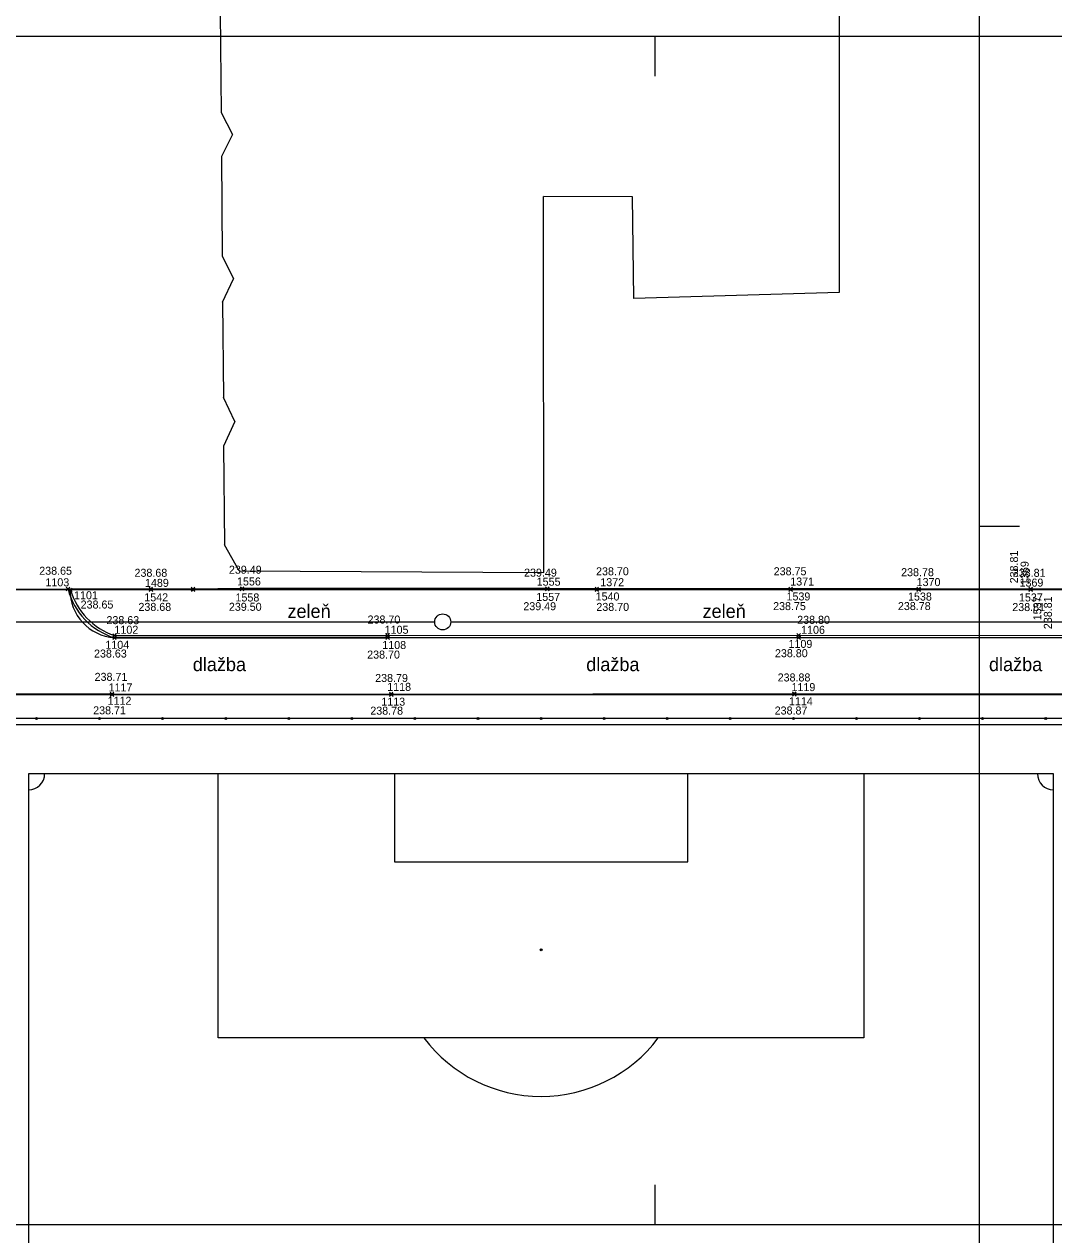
# Model space of a CAD drawing. Extents: x -264205 to -263659, y -1242401 to -1241986.
# Drawn here: x -264039.8 to -263975.5, y -1242219.8 to -1242144.2 of the extents above; entities that cross this region are included whole.
import ezdxf

# ---------------------------------------------------------------- set-up
doc = ezdxf.new("R2010")
doc.units = 0
for name, color, linetype in [('BOD_CISLO_2-1', 7, 'Continuous'), ('BOD_CISLO_2-3', 7, 'Continuous'), ('BOD_SYMBOL_2-1', 7, 'Continuous'), ('BOD_SYMBOL_2-3', 7, 'Continuous'), ('BOD_VYSKA_2-1', 7, 'Continuous'), ('BOD_VYSKA_2-3', 7, 'Continuous'), ('POPIS_2-1', 7, 'Continuous'), ('PROJEKT_OBRUBNIKY_KOMUNIKACIE', 7, 'Continuous'), ('RAM_NA_TLAC_2-1_1-250', 7, 'Continuous'), ('RAM_NA_TLAC_2-3_1-250', 7, 'Continuous'), ('SITUACIA_DSP_2D', 7, 'Continuous'), ('SO_20-4_OBRUBNIKY_HORNA_HRANA', 7, 'Continuous')]:
    doc.layers.add(name, color=color, linetype=linetype)

msp = doc.modelspace()

# ---------------------------------------------------------------- linework, layer by layer
at = {"layer": 'BOD_SYMBOL_2-1'}
for p, q in [((-264037.17, -1242179.556), (-264036.948, -1242179.336)), ((-264036.948, -1242179.556), (-264037.17, -1242179.336)), ((-264037.012, -1242179.6), (-264036.791, -1242179.38)), ((-264036.791, -1242179.6), (-264037.012, -1242179.38)), ((-264032, -1242179.555), (-264031.779, -1242179.333)), ((-264031.779, -1242179.555), (-264032, -1242179.333)), ((-264031.993, -1242179.603), (-264031.772, -1242179.383)), ((-264031.772, -1242179.603), (-264031.993, -1242179.383)), ((-264029.359, -1242179.559), (-264029.138, -1242179.338)), ((-264029.138, -1242179.559), (-264029.359, -1242179.338)), ((-264029.357, -1242179.6), (-264029.136, -1242179.379)), ((-264029.136, -1242179.6), (-264029.357, -1242179.379)), ((-264026.3, -1242179.565), (-264026.079, -1242179.343)), ((-264026.079, -1242179.565), (-264026.3, -1242179.343)), ((-264026.297, -1242179.519), (-264026.076, -1242179.299)), ((-264026.076, -1242179.519), (-264026.297, -1242179.299)), ((-264007.234, -1242179.525), (-264007.013, -1242179.305)), ((-264007.013, -1242179.525), (-264007.234, -1242179.305)), ((-264007.234, -1242179.566), (-264007.013, -1242179.346)), ((-264007.013, -1242179.566), (-264007.234, -1242179.346)), ((-264004.149, -1242179.552), (-264003.927, -1242179.33)), ((-264003.927, -1242179.552), (-264004.149, -1242179.33)), ((-264004.147, -1242179.599), (-264003.926, -1242179.377)), ((-264003.926, -1242179.599), (-264004.147, -1242179.377)), ((-263992.045, -1242179.593), (-263991.823, -1242179.372)), ((-263991.823, -1242179.593), (-263992.045, -1242179.372)), ((-263992.042, -1242179.546), (-263991.821, -1242179.325)), ((-263991.821, -1242179.546), (-263992.042, -1242179.325)), ((-263984.051, -1242179.595), (-263983.829, -1242179.373)), ((-263983.829, -1242179.595), (-263984.051, -1242179.373)), ((-263984.047, -1242179.551), (-263983.826, -1242179.329)), ((-263983.826, -1242179.551), (-263984.047, -1242179.329)), ((-263977.055, -1242179.556), (-263976.834, -1242179.335)), ((-263976.834, -1242179.556), (-263977.055, -1242179.335)), ((-263977.054, -1242179.603), (-263976.833, -1242179.382)), ((-263976.833, -1242179.603), (-263977.054, -1242179.382)), ((-264034.27, -1242182.455), (-264034.049, -1242182.235)), ((-264034.049, -1242182.455), (-264034.27, -1242182.235)), ((-264034.27, -1242182.602), (-264034.049, -1242182.38)), ((-264034.049, -1242182.602), (-264034.27, -1242182.38)), ((-264017.219, -1242182.458), (-264016.997, -1242182.237)), ((-264016.997, -1242182.458), (-264017.219, -1242182.237)), ((-264017.208, -1242182.597), (-264016.986, -1242182.377)), ((-264016.986, -1242182.597), (-264017.208, -1242182.377)), ((-263991.541, -1242182.44), (-263991.319, -1242182.218)), ((-263991.319, -1242182.44), (-263991.541, -1242182.218)), ((-263991.54, -1242182.588), (-263991.318, -1242182.367)), ((-263991.318, -1242182.588), (-263991.54, -1242182.367)), ((-264034.425, -1242186.103), (-264034.204, -1242185.882)), ((-264034.204, -1242186.103), (-264034.425, -1242185.882)), ((-264016.99, -1242186.115), (-264016.769, -1242185.894)), ((-264016.769, -1242186.115), (-264016.99, -1242185.894)), ((-263991.824, -1242186.088), (-263991.603, -1242185.867)), ((-263991.603, -1242186.088), (-263991.824, -1242185.867)), ((-264034.419, -1242186.149), (-264034.198, -1242185.927)), ((-264034.198, -1242186.149), (-264034.419, -1242185.927)), ((-264016.984, -1242186.16), (-264016.763, -1242185.94)), ((-264016.763, -1242186.16), (-264016.984, -1242185.94)), ((-263991.818, -1242186.133), (-263991.597, -1242185.913)), ((-263991.597, -1242186.133), (-263991.818, -1242185.913))]:
    msp.add_line(p, q, dxfattribs=at)
at = {"layer": 'BOD_SYMBOL_2-3'}
for p, q in [((-263976.834, -1242179.556), (-263977.055, -1242179.335)), ((-263976.834, -1242179.335), (-263977.055, -1242179.556)), ((-263976.833, -1242179.603), (-263977.054, -1242179.382)), ((-263976.833, -1242179.382), (-263977.054, -1242179.603))]:
    msp.add_line(p, q, dxfattribs=at)
at = {"layer": 'PROJEKT_OBRUBNIKY_KOMUNIKACIE'}
for p, q in [((-263959.468, -1242179.482), (-264131.568, -1242179.482)), ((-264131.568, -1242179.482), (-263959.468, -1242179.482)), ((-263959.468, -1242179.482), (-264077.23, -1242179.482)), ((-263960.118, -1242182.482), (-264034.158, -1242182.482))]:
    msp.add_line(p, q, dxfattribs=at)
msp.add_lwpolyline([(-264042.568, -1242294.032), (-263972.468, -1242294.032), (-263972.468, -1242187.932), (-264042.568, -1242187.932), (-264042.568, -1242294.032)], dxfattribs=at)
msp.add_arc((-264033.951, -1242179.495), 2.994, 179.74999, 266.03136, dxfattribs=at)
at = {"layer": 'RAM_NA_TLAC_2-1_1-250'}
for p, q in [((-264000.413, -1242144.907), (-264000.413, -1242147.407)), ((-264000.413, -1242216.657), (-264000.413, -1242219.157))]:
    msp.add_line(p, q, dxfattribs=at)
msp.add_lwpolyline([(-264147.913, -1242144.907), (-263857.913, -1242144.907), (-263857.913, -1242219.157), (-264147.913, -1242219.157)], close=True, dxfattribs=at)
at = {"layer": 'RAM_NA_TLAC_2-3_1-250'}
msp.add_line((-263980.139, -1242175.511), (-263977.639, -1242175.511), dxfattribs=at)
msp.add_lwpolyline([(-263980.139, -1242275.511), (-263980.139, -1241985.511), (-263905.889, -1241985.511), (-263905.889, -1242275.511)], close=True, dxfattribs=at)
at = {"layer": 'SITUACIA_DSP_2D'}
for p, q in [((-263988.88, -1242124.89), (-263988.91, -1242160.93)), ((-264027.55, -1242143.43), (-264027.5, -1242149.68)), ((-264027.5, -1242149.68), (-264026.79, -1242151.05)), ((-264026.79, -1242151.05), (-264027.48, -1242152.43)), ((-264027.48, -1242152.43), (-264027.43, -1242158.63)), ((-264007.37, -1242157.14), (-264007.36, -1242154.93)), ((-264001.8, -1242154.96), (-264007.36, -1242154.93)), ((-264001.73, -1242161.29), (-264001.8, -1242154.96)), ((-264007.34, -1242178.42), (-264007.37, -1242157.14)), ((-264027.43, -1242158.63), (-264026.72, -1242160.07)), ((-264027.41, -1242161.52), (-264026.72, -1242160.07)), ((-263988.91, -1242160.93), (-264001.73, -1242161.29)), ((-264027.41, -1242161.52), (-264027.36, -1242167.48)), ((-264026.65, -1242168.99), (-264027.36, -1242167.48)), ((-264026.65, -1242168.99), (-264027.34, -1242170.52)), ((-264027.34, -1242170.52), (-264027.29, -1242176.68)), ((-264026.37, -1242178.31), (-264027.29, -1242176.68)), ((-264026.37, -1242178.31), (-264007.34, -1242178.42)), ((-264131.568, -1242179.482), (-263959.468, -1242179.482)), ((-263959.468, -1242179.482), (-264131.568, -1242179.482)), ((-263959.468, -1242179.482), (-264077.23, -1242179.482)), ((-264041.667, -1242181.5), (-264014.161, -1242181.5)), ((-264013.161, -1242181.5), (-263964.161, -1242181.5)), ((-263960.118, -1242182.482), (-264034.158, -1242182.482)), ((-263972.068, -1242187.532), (-264118.068, -1242187.532)), ((-263972.468, -1242187.932), (-264042.568, -1242187.932)), ((-264039.089, -1242187.532), (-264038.969, -1242187.532)), ((-264039.029, -1242187.592), (-264039.029, -1242187.472)), ((-264035.15, -1242187.532), (-264035.03, -1242187.532)), ((-264035.09, -1242187.592), (-264035.09, -1242187.472)), ((-264031.211, -1242187.532), (-264031.091, -1242187.532)), ((-264031.151, -1242187.592), (-264031.151, -1242187.472)), ((-264027.272, -1242187.532), (-264027.152, -1242187.532)), ((-264027.212, -1242187.592), (-264027.212, -1242187.472)), ((-264023.333, -1242187.532), (-264023.213, -1242187.532)), ((-264023.273, -1242187.592), (-264023.273, -1242187.472)), ((-264019.394, -1242187.532), (-264019.274, -1242187.532)), ((-264019.334, -1242187.592), (-264019.334, -1242187.472)), ((-264015.456, -1242187.532), (-264015.336, -1242187.532)), ((-264015.396, -1242187.592), (-264015.396, -1242187.472)), ((-264011.517, -1242187.532), (-264011.397, -1242187.532)), ((-264011.457, -1242187.592), (-264011.457, -1242187.472)), ((-264007.578, -1242187.532), (-264007.458, -1242187.532)), ((-264007.518, -1242187.592), (-264007.518, -1242187.472)), ((-264003.639, -1242187.532), (-264003.519, -1242187.532)), ((-264003.579, -1242187.592), (-264003.579, -1242187.472)), ((-263999.7, -1242187.532), (-263999.58, -1242187.532)), ((-263999.64, -1242187.592), (-263999.64, -1242187.472)), ((-263995.761, -1242187.532), (-263995.641, -1242187.532)), ((-263995.701, -1242187.592), (-263995.701, -1242187.472)), ((-263991.822, -1242187.532), (-263991.702, -1242187.532)), ((-263991.762, -1242187.592), (-263991.762, -1242187.472)), ((-263987.883, -1242187.532), (-263987.763, -1242187.532)), ((-263987.823, -1242187.592), (-263987.823, -1242187.472)), ((-263983.944, -1242187.532), (-263983.824, -1242187.532)), ((-263983.884, -1242187.592), (-263983.884, -1242187.472)), ((-263980.006, -1242187.532), (-263979.886, -1242187.532)), ((-263979.946, -1242187.592), (-263979.946, -1242187.472)), ((-263976.067, -1242187.532), (-263975.947, -1242187.532)), ((-263976.007, -1242187.592), (-263976.007, -1242187.472)), ((-263975.518, -1242190.982), (-264039.518, -1242190.982)), ((-264039.518, -1242190.982), (-264039.518, -1242290.982)), ((-264027.678, -1242207.482), (-264027.678, -1242190.982)), ((-264016.678, -1242190.982), (-264016.678, -1242196.482)), ((-263998.358, -1242196.482), (-263998.358, -1242190.982)), ((-263987.358, -1242190.982), (-263987.358, -1242207.482)), ((-263975.518, -1242290.982), (-263975.518, -1242190.982)), ((-264016.678, -1242196.482), (-263998.358, -1242196.482)), ((-263987.358, -1242207.482), (-264027.678, -1242207.482))]:
    msp.add_line(p, q, dxfattribs=at)
for centre, radius in [((-264013.661, -1242181.5), 0.5), ((-264039.029, -1242187.532), 0.06), ((-264035.09, -1242187.532), 0.06), ((-264031.151, -1242187.532), 0.06), ((-264027.212, -1242187.532), 0.06), ((-264023.273, -1242187.532), 0.06), ((-264019.334, -1242187.532), 0.06), ((-264015.396, -1242187.532), 0.06), ((-264011.457, -1242187.532), 0.06), ((-264007.518, -1242187.532), 0.06), ((-264003.579, -1242187.532), 0.06), ((-263999.64, -1242187.532), 0.06), ((-263995.701, -1242187.532), 0.06), ((-263991.762, -1242187.532), 0.06), ((-263987.823, -1242187.532), 0.06), ((-263983.884, -1242187.532), 0.06), ((-263979.946, -1242187.532), 0.06), ((-263976.007, -1242187.532), 0.06), ((-264007.518, -1242201.982), 0.06)]:
    msp.add_circle(centre, radius, dxfattribs=at)
for centre, radius, start, end in [((-264033.951, -1242179.495), 2.994, 179.74999, 266.03136), ((-264039.518, -1242190.982), 1, 270, 360), ((-263975.518, -1242190.982), 1, 180, 270), ((-264007.518, -1242201.982), 0.0303, 90, 270), ((-264007.518, -1242201.982), 0.0303, 270, 90), ((-264007.518, -1242201.982), 9.15, 216.94821, 323.05179)]:
    msp.add_arc(centre, radius, start, end, dxfattribs=at)
at = {"layer": 'SO_20-4_OBRUBNIKY_HORNA_HRANA'}
for points in [[(-264029.248, -1242179.448), (-264031.889, -1242179.444), (-264037.059, -1242179.446)], [(-264029.247, -1242179.489), (-264031.883, -1242179.493), (-264036.901, -1242179.49)], [(-264004.038, -1242179.441), (-264007.123, -1242179.415), (-264026.187, -1242179.409), (-264029.248, -1242179.448)], [(-264004.036, -1242179.488), (-264007.123, -1242179.456), (-264026.189, -1242179.454), (-264029.247, -1242179.489)], [(-263959.501, -1242179.449), (-263965.95, -1242179.446), (-263969.95, -1242179.443), (-263976.944, -1242179.445), (-263983.937, -1242179.44), (-263991.932, -1242179.435), (-264004.038, -1242179.441)], [(-263959.457, -1242179.496), (-263965.955, -1242179.491), (-263969.948, -1242179.491), (-263976.943, -1242179.492), (-263983.94, -1242179.484), (-263991.934, -1242179.482), (-264004.036, -1242179.488)], [(-264034.16, -1242182.345), (-264017.108, -1242182.347), (-263991.43, -1242182.329), (-263971.154, -1242182.338)], [(-264034.16, -1242182.491), (-264017.097, -1242182.487), (-263991.429, -1242182.477), (-263971.157, -1242182.481)], [(-264052.662, -1242185.992), (-264034.314, -1242185.992), (-264016.879, -1242186.004), (-263991.714, -1242185.977), (-263970.772, -1242185.99)], [(-264052.656, -1242186.038), (-264034.308, -1242186.038), (-264016.873, -1242186.05), (-263991.708, -1242186.023), (-263970.772, -1242186.036)]]:
    msp.add_lwpolyline(points, dxfattribs=at)
for centre, major_axis, ratio, start_param, end_param in [((-264032.88, -1242178.369), (-3.709, -2.207), 0.999982, 5.998548, 7.016178), ((-264032.845, -1242178.339), (-2.235, -3.575), 0.999976, 5.547555, 6.524758)]:
    msp.add_ellipse(centre, major_axis=major_axis, ratio=ratio, start_param=start_param, end_param=end_param, dxfattribs=at)

# ---------------------------------------------------------------- texts
at = {"layer": 'BOD_CISLO_2-1'}
for s, p in [('1103', (-264038.471, -1242179.274)), ('1489', (-264032.253, -1242179.309)), ('1556', (-264026.505, -1242179.22)), ('1555', (-264007.792, -1242179.236)), ('1372', (-264003.819, -1242179.268)), ('1371', (-263991.957, -1242179.225)), ('1370', (-263984.065, -1242179.259)), ('1369', (-263977.639, -1242179.293)), ('1101', (-264036.682, -1242180.083)), ('1542', (-264032.295, -1242180.211)), ('1558', (-264026.601, -1242180.222)), ('1557', (-264007.819, -1242180.187)), ('1540', (-264004.111, -1242180.16)), ('1539', (-263992.191, -1242180.157)), ('1538', (-263984.603, -1242180.164)), ('1537', (-263977.674, -1242180.219)), ('1102', (-264034.16, -1242182.236)), ('1105', (-264017.286, -1242182.238)), ('1106', (-263991.28, -1242182.242)), ('1104', (-264034.727, -1242183.178)), ('1108', (-264017.434, -1242183.189)), ('1109', (-263992.066, -1242183.121)), ('1117', (-264034.528, -1242185.841)), ('1118', (-264017.125, -1242185.803)), ('1119', (-263991.88, -1242185.82)), ('1112', (-264034.586, -1242186.671)), ('1113', (-264017.494, -1242186.729)), ('1114', (-263992.038, -1242186.702))]:
    msp.add_text(s, height=0.5, dxfattribs=at).set_placement(p)
at = {"layer": 'BOD_CISLO_2-3'}
for s, p in [('1369', (-263977.073, -1242179.19)), ('1537', (-263976.28, -1242181.396))]:
    msp.add_text(s, height=0.5, rotation=90, dxfattribs=at).set_placement(p)
at = {"layer": 'BOD_VYSKA_2-1'}
for s, p in [('238.65', (-264038.858, -1242178.552)), ('238.68', (-264032.908, -1242178.679)), ('239.49', (-264027.012, -1242178.488)), ('239.49', (-264008.581, -1242178.671)), ('238.70', (-264004.085, -1242178.585)), ('238.75', (-263992.992, -1242178.584)), ('238.78', (-263985.034, -1242178.642)), ('238.81', (-263978.06, -1242178.682)), ('238.65', (-264036.272, -1242180.662)), ('238.68', (-264032.662, -1242180.81)), ('239.50', (-264027.014, -1242180.803)), ('239.49', (-264008.626, -1242180.767)), ('238.70', (-264004.067, -1242180.81)), ('238.75', (-263993.029, -1242180.761)), ('238.78', (-263985.235, -1242180.758)), ('238.81', (-263978.092, -1242180.821)), ('238.63', (-264034.66, -1242181.638)), ('238.70', (-264018.354, -1242181.598)), ('238.80', (-263991.524, -1242181.617)), ('238.63', (-264035.436, -1242183.724)), ('238.70', (-264018.377, -1242183.788)), ('238.80', (-263992.913, -1242183.701)), ('238.71', (-264035.399, -1242185.178)), ('238.79', (-264017.879, -1242185.249)), ('238.88', (-263992.745, -1242185.217)), ('238.71', (-264035.489, -1242187.269)), ('238.78', (-264018.183, -1242187.292)), ('238.87', (-263992.931, -1242187.281))]:
    msp.add_text(s, height=0.5, dxfattribs=at).set_placement(p)
at = {"layer": 'BOD_VYSKA_2-3'}
for p in [(-263977.737, -1242179.09), (-263975.621, -1242181.95)]:
    msp.add_text('238.81', height=0.5, rotation=90, dxfattribs=at).set_placement(p)
at = {"layer": 'POPIS_2-1'}
for s, p in [('zeleň', (-264023.355, -1242181.251)), ('zeleň', (-263997.433, -1242181.251)), ('dlažba', (-264029.268, -1242184.573)), ('dlažba', (-264004.698, -1242184.573)), ('dlažba', (-263979.548, -1242184.573))]:
    msp.add_text(s, height=0.8438, dxfattribs=at).set_placement(p)

doc.saveas('drawing.dxf')
